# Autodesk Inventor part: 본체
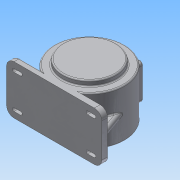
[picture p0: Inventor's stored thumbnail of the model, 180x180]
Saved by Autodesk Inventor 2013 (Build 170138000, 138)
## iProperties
Created: 2015-06
Part Number: 본체
Material: 알루미늄 6061
Document SubType Name: Modeling
Designer: dgall
Density: 2.71 g/cm^3
Mass: 3328.83 g
Surface Area: 2328.01 cm^2
Volume: 1228.35 cm^3
Author: dgall
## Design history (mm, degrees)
sketch "스케치1"
  geometry: L1 (-115, 59)-(115, 59); L2 (115, 59)-(115, -59); L3 (115, -59)-(-115, -59); L4 (-115, -59)-(-115, 59); 5 further points
  constraints: 8 end point, 4 midpoint, 2 horizontal alignment, 2 parallel, 2 vertical alignment, 1 horizontal, 1 perpendicular
  dimensions: "d0" = 230 distance of L1.start L1.end; "d2" = 118 distance of L1.end L2.end
extrude "돌출1" new body sketch "스케치1" distance "d3" = 14; taper "d4" = 0 deg
sketch "스케치2"
  geometry: L1 (14, -59)-(14, 59) reference; L2 (85, 59)-(85, -59); L3 (0, 59)-(0, -59) reference; L4 (85, 59)-(170, 59); L5 (170, 59)-(170, -59); L6 (170, -59)-(85, -59); L7 (162, -51)-(162, 51); L8 (162, 51)-(85, 51); L9 (85, -51)-(162, -51); L10 (116, 51)-(114.368, 47.5); L11 (85, 47.5)-(114.368, 47.5); L12 (85, 51)-(85, 47.5); 1 further point
  constraints: 20 end point, 4 parallel, 4 point on line, 3 perpendicular, 1 collinear, 1 horizontal alignment
  dimensions: "d5" = 85 distance between parallel lines of L3 L2; "d6" = 170 diameter of L5 L2; "d7" = 118 distance between parallel lines of L6 L4; "d8" = 118 distance of L3.start L3.end (derived); "d9" = 8 distance between parallel lines of L7 L5; "d10" = 102 distance between parallel lines of L9 L8; "d11" = 8 distance between parallel lines of L8 L4; "d36" = 115 deg angle of L8 L10; "d37" = 62 diameter of L10.start L2; "d38" = 3.5 distance between parallel lines of L11 L8
revolve "회전1" stored, may be unused: angle "d12" = 90 deg
sketch "스케치3"
  geometry: C1 r 65 at (115, 85); A1 r 85 centre (115, 85) between (161.733, 14) and (68.267, 14) reference; 1 further point
  constraints: 1 centre point, 1 coincident
  dimensions: "d13" = 130 diameter of C1
extrude "돌출2" join sketch "스케치3" distance "d15" = 13; taper "d16" = 0 deg
sketch "스케치4"
  geometry: C1 r 65 at (115, 85); A1 r 85 centre (115, 85) between (161.733, 14) and (68.267, 14) reference; 1 further point
  constraints: 1 centre point, 1 coincident
  dimensions: "d17" = 130 diameter of C1
extrude "돌출3" join sketch "스케치4" distance "d19" = 3; taper "d20" = 0 deg
sketch "스케치5"
  geometry: C1 r 65 at (0, 0) reference; C2 r 47.5 at (0, 0); 1 further point
  constraints: 1 centre point, 1 coincident
  dimensions: "d21" = 95 diameter of C2
extrude "돌출4" cut sketch "스케치5" distance "d23" = 20; taper "d24" = 0 deg
node "스케치6"
revolve "회전2" stored, may be unused: angle "d39" = 90 deg
sketch "스케치7" dims "d40" = 110
  geometry: C1 r 47.5 at (0, 0) reference; C2 r 65 at (0, 0) reference; 3 further points
  constraints: 2 vertical alignment, 1 coincident, 2 other
hole "구멍1" sketch "스케치7" at (0, 55) diameter "d42" = 3.242; stored, may be unused: countersink angle "d46" = 90 deg, drill point angle "d48" = 118 deg; dims "d43" = 13, "d44" = 3.6, "d45" = 2, "d47" = 15
sketch "스케치8"
  geometry: C1 r 29.368 at (0, 0) reference; C2 r 23.5 at (0, 0); C3 r 15 at (0, 0); 1 further point
  constraints: 2 centre point, 2 coincident
  dimensions: "d52" = 47 diameter of C2; "d54" = 30 diameter of C3
extrude "돌출5" cut sketch "스케치8" distance "d55" = 14; taper "d56" = 0 deg
extrude "돌출6" cut sketch "스케치8" distance "d57" = 17; taper "d58" = 0 deg
sketch "스케치9"
  geometry: L1 (-115, 59)-(115, 59) reference; L2 (-115, -59)-(-115, 59) reference; L3 (-97, 45)-(-81, 45); L4 (-97, 37)-(-81, 37); L5 (-81, 50)-(-97, 50); L6 (-97, 32)-(-81, 32); A1 r 4 centre (-97, 41) between (-97, 45) and (-97, 37); A2 r 4 centre (-81, 41) between (-81, 37) and (-81, 45); A3 r 9 centre (-97, 41) between (-97, 50) and (-97, 32); A4 r 9 centre (-81, 41) between (-81, 32) and (-81, 50); 1 further point
  constraints: 8 end point, 8 point on circle, 4 centre point, 4 tangent, 1 equal radius, 1 horizontal alignment, 3 other
  dimensions: "d59" = 18 distance from line of L1 A1.centre; "d60" = 18 distance from line of L2 A1.centre; "d61" = 16 distance of A2.centre A1.centre; "d62" = 8 diameter of A1; "d63" = 18 distance between parallel lines of L6 L5
extrude "돌출7" join sketch "스케치9" distance "d64" = 3; taper "d65" = 0 deg
sketch "스케치10"
  geometry: L1 (-81, 50)-(-97, 50) reference; L2 (-97, 32)-(-81, 32) reference; L3 (-97, 45)-(-81, 45); L4 (-81, 37)-(-97, 37); A1 r 9 centre (-97, 41) between (-97, 50) and (-97, 32) reference; A2 r 9 centre (-81, 41) between (-81, 32) and (-81, 50) reference; A3 r 4 centre (-81, 41) between (-81, 37) and (-81, 45); A4 r 4 centre (-97, 41) between (-97, 45) and (-97, 37); 1 further point
  constraints: 4 end point, 4 point on circle, 2 centre point, 3 other
  dimensions: "d66" = 8 distance between parallel lines of L4 L3
extrude "돌출8" cut sketch "스케치10" stored distance "d68" = 3; taper "d69" = 0 deg
node "작업 평면1"
sketch "스케치11"
  geometry: L1 (42.5, 42.5)-(-42.5, 42.5); L2 (-42.5, 42.5)-(-42.5, -42.5); L3 (-42.5, -42.5)-(42.5, -42.5); L4 (42.5, -42.5)-(42.5, 42.5); C1 r 35 at (0, 0); 5 further points
  constraints: 8 end point, 4 midpoint, 2 horizontal alignment, 2 parallel, 2 vertical alignment, 1 centre point, 1 coincident, 1 horizontal, 1 perpendicular
  dimensions: "d71" = 85 distance of L1.start L1.end; "d73" = 85 distance between parallel lines of L3 L1; "d74" = 70 diameter of C1
extrude "돌출9" join sketch "스케치11" stored distance "d75" = 3; taper "d76" = 0 deg
extrude "돌출10" cut sketch "스케치11" stored distance "d77" = 3; taper "d78" = 0 deg
sketch "스케치12"
  geometry: L1 (-42.5, 42.5)-(42.5, 42.5) reference; L2 (-42.5, -42.5)-(-42.5, 42.5) reference; 1 further point
  dimensions: "d81" = 7 distance from line of L2 point (-35.5, 35.5); "d82" = 7 distance from line of L1 point (-35.5, 35.5)
hole "구멍2" sketch "스케치12" at (-35.5, 35.5) diameter "d83" = 3.242; stored, may be unused: countersink angle "d87" = 90 deg, drill point angle "d89" = 118 deg; dims "d84" = 10, "d85" = 3.6, "d86" = 2, "d88" = 13
node "작업 평면2"
sketch "스케치13"
  geometry: L1 (68.267, 14)-(0, 14) reference; L2 (6, 14)-(30.13, 80.297); A1 r 85 centre (115, 85) between (161.733, 14) and (68.267, 14) reference; 1 further point
  constraints: 2 end point, 1 point on circle, 1 point on line
  dimensions: "d97" = 6 distance of L2.start L1.end; "d98" = 110 deg angle of L2 L1
feature "리브1" sketch "스케치13" dims "d99" = 1, "d100" = 15, "d101" = 0, "d102" = 0, "d103" = 1, "d104" = 1
fillet "모깎기1" dims "d105" = 3
fillet "모깎기2" dims "d106" = 18
fillet "모깎기3"
fillet "모깎기4"
fillet "모깎기5" dims "d107" = 7
fillet "모깎기6" dims "d108" = 3
fillet "모깎기7" dims "d109" = 3
fillet "모깎기8" dims "d110" = 3
chamfer "모따기1" distance "d111" = 1; stored, may be unused: second distance "d112" = 2, angle "d113" = 45 deg
fillet "모깎기9" dims "d114" = 0.3
fillet "모깎기10" dims "d115" = 3
chamfer "모따기2" distance "d116" = 1; stored, may be unused: second distance "d117" = 2, angle "d118" = 45 deg
fillet "모깎기11" dims "d119" = 3
node "솔리드1"
pattern_circular "원형 패턴1" dims angle "d50" = 360 deg
mirror "대칭1"
mirror "대칭2"
pattern_linear "직사각형 패턴1" dims "d92" = 71, "d95" = 71
mirror "대칭3"
other parameters: "d70" = -173, "d96" = -59
